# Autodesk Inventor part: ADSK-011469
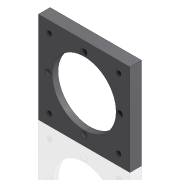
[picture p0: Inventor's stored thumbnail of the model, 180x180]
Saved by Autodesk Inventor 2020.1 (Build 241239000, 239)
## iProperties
Created: 2000-01
Part Number: ADSK-011469
Material: Acier doux
Document SubType Name: Modeling
Designer: glanglot
Density: 7.86 g/cm^3
Appearance: Metal-Steel(Polish)
Mass: 460.764 g
Surface Area: 216.906 cm^2
Volume: 58.6214 cm^3
Control State: 0
Checked Out: False
Master: False
Shininess: 0.0
Length Units: 11269
Angle Units: 11279
Time Units: 11290
Mass Units: 11283
Length Display Precision: 5
Angle Display Precision: 5
Compacted: True
Cutlength: 4
Material Desc: FLAT,HRS,0.500X04.000
Material_Number: A084316
Dimensions: 100x100x12,7 mm
Mass: 0,461 kg
DocNumber: ADSK-011469.ipt
Folder: 01 - Themengebiete\Simplification\01 - Packaging machine\
VDS_Category: 3D Komponenten
Density: 0.0
Volumn: 0.0
Area: 0.0
PropertySet Name: Model Information
Author: glanglot
Revision Number: -
Title: plate
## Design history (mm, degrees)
node "Solide1"
  node "Extrusion1" dims "d11" = 12.7, "d12" = 0
  node "Hole1" dims "d13" = 6.6, "d14" = 9.525, "d15" = 6.35, "d16" = 60 deg, "d17" = 19.05, "d18" = 118 deg, "d36" = 6
  node "Hole2" dims "d22" = 4.917, "d23" = 9.525, "d24" = 6.35, "d25" = 60 deg, "d26" = 17.1, "d27" = 118 deg, "d37" = 12
  node "Extrusion2" dims "d30" = 6.35, "d31" = 0
sketch "Sketch1"
  geometry: L1 (0, 100)-(100, 100); L2 (100, 100)-(100, 0); L3 (100, 0)-(0, 0); L4 (0, 0)-(0, 100); L5 (50, 100)-(50, 0); L6 (100, 50)-(0, 50); L7 (12, 88)-(88, 88); L8 (88, 88)-(88, 12); L9 (88, 12)-(12, 12); L10 (12, 12)-(12, 88); C1 r 34.925 at (50, 50); 8 further points
  constraints: 20 end point, 6 midpoint, 5 point on line, 4 parallel, 3 coincident, 2 horizontal, 2 perpendicular, 1 centre point
  dimensions: "d0" = 100 distance of L3.end L1.start; "d1" = 100 distance of L1.start L1.end (= d0); "d19" = 40 distance from line of L5 point (10, 50) (= d20); "d20" = 40 distance from line of L6 point (50, 10) (= d34); "d28" = 69.85 diameter of C1; "d32" = 76 distance of L7.start L7.end; "d33" = 76 distance of L7.end L8.end; "d34" = 40 distance from line of L6 point (50, 90); "d35" = 40 distance from line of L5 point (90, 50) (= d34)
node "Corps solides"
node "Corps surfaciques"
sketch "Sketch2"
  geometry: C1 r 3.572 at (-50.8, 90.8) reference; C2 r 3.3 at (-10, 50) reference; C3 r 3.3 at (-50, 10) reference; C4 r 3.3 at (-90, 50) reference; C5 r 34.925 at (-50, 50) reference; C6 r 46.037 at (-50, 50)
  constraints: 1 centre point, 1 coincident
  dimensions: "d29" = 92.075 diameter of C6
